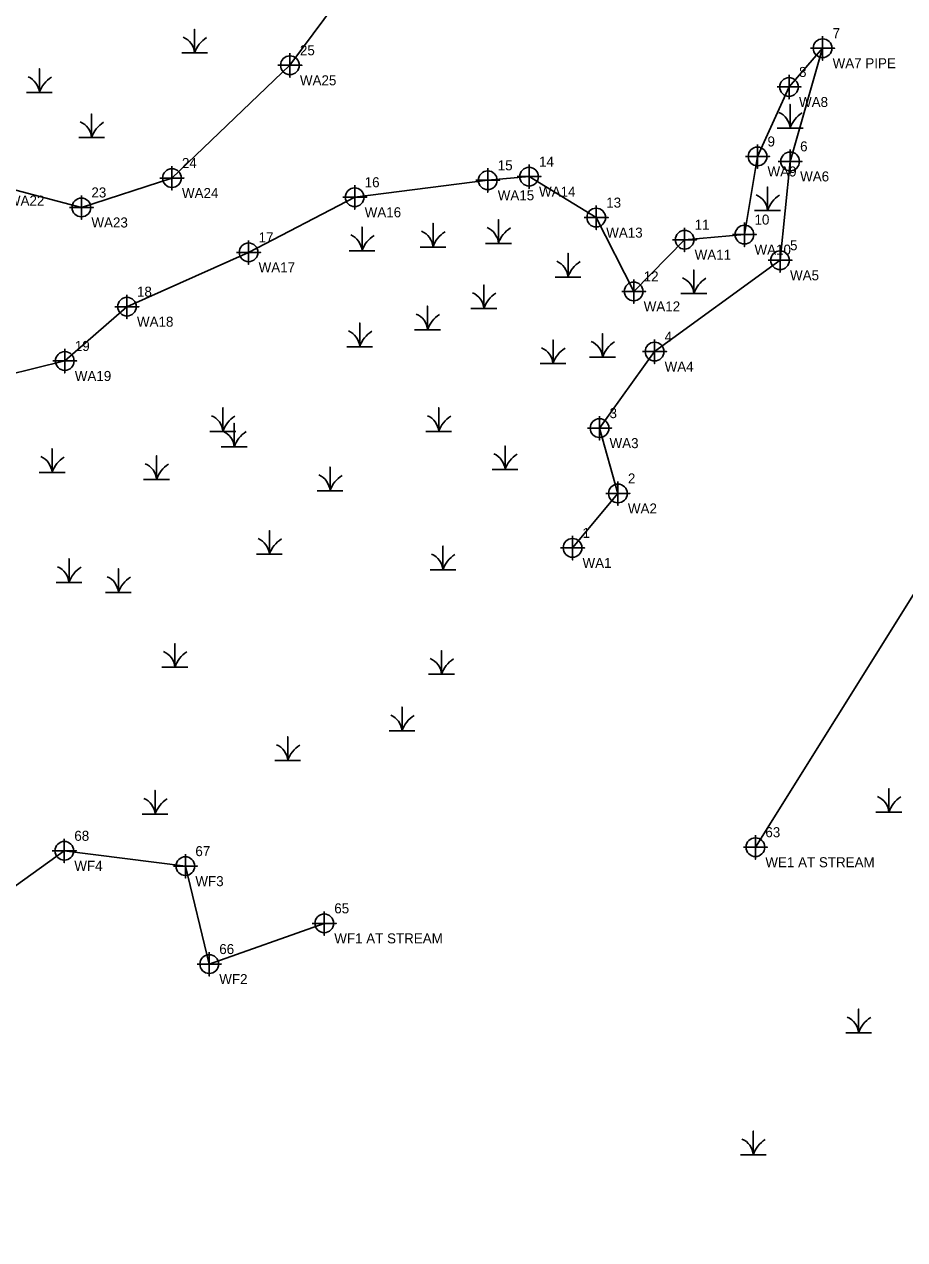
# Model space of a CAD drawing. Extents: x 2189822 to 2191198, y 387253 to 388663.
# Drawn here: x 2190236.7 to 2190456.6, y 387833.3 to 388136.9 of the extents above; entities that cross this region are included whole.
import ezdxf

# ---------------------------------------------------------------- set-up
doc = ezdxf.new("R2010")
doc.units = 0
for name, color, linetype in [('Structure020030_Alleghany', 7, 'Continuous'), ('Structure040008_Ashe', 7, 'Continuous'), ('Structure090007_Brunswick', 7, 'Continuous'), ('Structure620024_Moore', 7, 'Continuous'), ('Structure780124_Rockingham', 7, 'Continuous')]:
    doc.layers.add(name, color=color, linetype=linetype)

msp = doc.modelspace()

# ---------------------------------------------------------------- linework, layer by layer
at = {"layer": 'Structure020030_Alleghany'}
for points in [[(2190436.1, 388133.93), (2190436.1, 388127.93), (2190436.1, 388130.93), (2190439.1, 388130.93), (2190433.1, 388130.93)], [(2190303.02, 388129.66), (2190303.02, 388123.66), (2190303.02, 388126.66), (2190306.02, 388126.66), (2190300.02, 388126.66)], [(2190427.71, 388124.24), (2190427.71, 388118.24), (2190427.71, 388121.24), (2190430.71, 388121.24), (2190424.71, 388121.24)], [(2190419.84, 388106.88), (2190419.84, 388100.88), (2190419.84, 388103.88), (2190422.84, 388103.88), (2190416.84, 388103.88)], [(2190427.98, 388105.65), (2190427.98, 388099.65), (2190427.98, 388102.65), (2190430.98, 388102.65), (2190424.98, 388102.65)], [(2190273.55, 388101.49), (2190273.55, 388095.49), (2190273.55, 388098.49), (2190276.55, 388098.49), (2190270.55, 388098.49)], [(2190352.44, 388100.93), (2190352.44, 388094.93), (2190352.44, 388097.93), (2190355.44, 388097.93), (2190349.44, 388097.93)], [(2190362.76, 388101.84), (2190362.76, 388095.84), (2190362.76, 388098.84), (2190365.76, 388098.84), (2190359.76, 388098.84)], [(2190250.93, 388094.14), (2190250.93, 388088.14), (2190250.93, 388091.14), (2190253.93, 388091.14), (2190247.93, 388091.14)], [(2190319.2, 388096.69), (2190319.2, 388090.69), (2190319.2, 388093.69), (2190322.2, 388093.69), (2190316.2, 388093.69)], [(2190379.54, 388091.61), (2190379.54, 388085.61), (2190379.54, 388088.61), (2190382.54, 388088.61), (2190376.54, 388088.61)], [(2190401.63, 388086.09), (2190401.63, 388080.09), (2190401.63, 388083.09), (2190404.63, 388083.09), (2190398.63, 388083.09)], [(2190416.58, 388087.36), (2190416.58, 388081.36), (2190416.58, 388084.36), (2190419.58, 388084.36), (2190413.58, 388084.36)], [(2190292.7, 388082.93), (2190292.7, 388076.93), (2190292.7, 388079.93), (2190295.7, 388079.93), (2190289.7, 388079.93)], [(2190425.46, 388080.95), (2190425.46, 388074.95), (2190425.46, 388077.95), (2190428.46, 388077.95), (2190422.46, 388077.95)], [(2190388.9, 388073.17), (2190388.9, 388067.17), (2190388.9, 388070.17), (2190391.9, 388070.17), (2190385.9, 388070.17)], [(2190262.31, 388069.36), (2190262.31, 388063.36), (2190262.31, 388066.36), (2190265.31, 388066.36), (2190259.31, 388066.36)], [(2190394.13, 388058.14), (2190394.13, 388052.14), (2190394.13, 388055.14), (2190397.13, 388055.14), (2190391.13, 388055.14)], [(2190246.78, 388055.8), (2190246.78, 388049.8), (2190246.78, 388052.8), (2190249.78, 388052.8), (2190243.78, 388052.8)], [(2190380.37, 388039.02), (2190380.37, 388033.02), (2190380.37, 388036.02), (2190383.37, 388036.02), (2190377.37, 388036.02)], [(2190384.96, 388022.7), (2190384.96, 388016.7), (2190384.96, 388019.7), (2190387.96, 388019.7), (2190381.96, 388019.7)], [(2190373.62, 388009.11), (2190373.62, 388003.11), (2190373.62, 388006.11), (2190376.62, 388006.11), (2190370.62, 388006.11)], [(2190246.66, 387933.44), (2190246.66, 387927.44), (2190246.66, 387930.44), (2190249.66, 387930.44), (2190243.66, 387930.44)], [(2190419.3, 387934.34), (2190419.3, 387928.34), (2190419.3, 387931.34), (2190422.3, 387931.34), (2190416.3, 387931.34)], [(2190276.9, 387929.61), (2190276.9, 387923.61), (2190276.9, 387926.61), (2190279.9, 387926.61), (2190273.9, 387926.61)], [(2190311.6, 387915.32), (2190311.6, 387909.32), (2190311.6, 387912.32), (2190314.6, 387912.32), (2190308.6, 387912.32)], [(2190282.87, 387905.15), (2190282.87, 387899.15), (2190282.87, 387902.15), (2190285.87, 387902.15), (2190279.87, 387902.15)]]:
    msp.add_lwpolyline(points, dxfattribs=at)
for centre in [(2190436.1, 388130.93), (2190303.02, 388126.66), (2190427.71, 388121.24), (2190419.84, 388103.88), (2190427.98, 388102.65), (2190273.55, 388098.49), (2190352.44, 388097.93), (2190362.76, 388098.84), (2190319.2, 388093.69), (2190250.93, 388091.14), (2190379.54, 388088.61), (2190401.63, 388083.09), (2190416.58, 388084.36), (2190292.7, 388079.93), (2190425.46, 388077.95), (2190388.9, 388070.17), (2190262.31, 388066.36), (2190394.13, 388055.14), (2190246.78, 388052.8), (2190380.37, 388036.02), (2190384.96, 388019.7), (2190373.62, 388006.11), (2190246.66, 387930.44), (2190419.3, 387931.34), (2190276.9, 387926.61), (2190311.6, 387912.32), (2190282.87, 387902.15)]:
    msp.add_circle(centre, 2.34, dxfattribs=at)
at = {"layer": 'Structure620024_Moore'}
for points in [[(2190230.07, 388096.61), (2190250.93, 388091.14), (2190273.55, 388098.49), (2190303.02, 388126.66), (2190317.29, 388145.97)], [(2190373.62, 388006.11), (2190384.96, 388019.7), (2190380.37, 388036.02), (2190394.13, 388055.14), (2190425.46, 388077.95), (2190427.98, 388102.65), (2190436.1, 388130.93), (2190427.71, 388121.24), (2190419.84, 388103.88), (2190416.58, 388084.36), (2190401.63, 388083.09), (2190388.9, 388070.17), (2190379.54, 388088.61), (2190362.76, 388098.84), (2190352.44, 388097.93), (2190319.2, 388093.69), (2190292.7, 388079.93), (2190262.31, 388066.36), (2190246.78, 388052.8), (2190217.1, 388045.51)], [(2190419.3, 387931.34), (2190459.66, 387995.83)], [(2190311.6, 387912.32), (2190282.87, 387902.15), (2190276.9, 387926.61), (2190246.66, 387930.44), (2190212.31, 387905.81), (2190187.82, 387866.13), (2190141.4, 387841.78), (2190098.41, 387819.25)]]:
    msp.add_lwpolyline(points, dxfattribs=at)
at = {"layer": 'Structure780124_Rockingham'}
for p, q in [((2190279.21, 388132.42), (2190279.21, 388132.42)), ((2190240.43, 388122.54), (2190240.43, 388122.54)), ((2190427.98, 388113.65), (2190427.98, 388113.65)), ((2190253.47, 388111.25), (2190253.47, 388111.25)), ((2190422.34, 388093.03), (2190422.34, 388093.03)), ((2190355.11, 388084.86), (2190355.11, 388084.86)), ((2190321.04, 388083.01), (2190321.04, 388083.01)), ((2190338.77, 388083.93), (2190338.77, 388083.93)), ((2190372.49, 388076.45), (2190372.49, 388076.45)), ((2190403.92, 388072.3), (2190403.92, 388072.3)), ((2190351.48, 388068.57), (2190351.48, 388068.57)), ((2190337.38, 388063.28), (2190337.38, 388063.28)), ((2190320.45, 388059.05), (2190320.45, 388059.05)), ((2190368.75, 388054.81), (2190368.75, 388054.81)), ((2190381.13, 388056.4), (2190381.13, 388056.4)), ((2190286.26, 388037.88), (2190286.26, 388037.88)), ((2190340.2, 388037.88), (2190340.2, 388037.88)), ((2190289.08, 388034), (2190289.08, 388034)), ((2190243.6, 388027.65), (2190243.6, 388027.65)), ((2190356.76, 388028.36), (2190356.76, 388028.36)), ((2190269.69, 388025.89), (2190269.69, 388025.89)), ((2190313.05, 388023.06), (2190313.05, 388023.06)), ((2190297.89, 388007.19), (2190297.89, 388007.19)), ((2190341.25, 388003.31), (2190341.25, 388003.31)), ((2190247.83, 388000.14), (2190247.83, 388000.14)), ((2190260.17, 387997.67), (2190260.17, 387997.67)), ((2190274.27, 387978.97), (2190274.27, 387978.97)), ((2190340.9, 387977.21), (2190340.9, 387977.21)), ((2190331.03, 387963.1), (2190331.03, 387963.1)), ((2190302.48, 387955.69), (2190302.48, 387955.69)), ((2190269.34, 387942.28), (2190269.34, 387942.28)), ((2190452.66, 387942.75), (2190452.66, 387942.75)), ((2190445.1, 387887.65), (2190445.1, 387887.65)), ((2190418.77, 387857.2), (2190418.77, 387857.2))]:
    msp.add_line(p, q, dxfattribs=at)
for points in [[(2190275.98, 388129.74), (2190279.21, 388129.74), (2190279.21, 388135.66), (2190279.21, 388129.74), (2190282.44, 388129.74)], [(2190237.21, 388119.87), (2190240.43, 388119.87), (2190240.43, 388125.78), (2190240.43, 388119.87), (2190243.66, 388119.87)], [(2190424.75, 388110.98), (2190427.98, 388110.98), (2190427.98, 388116.89), (2190427.98, 388110.98), (2190431.2, 388110.98)], [(2190250.25, 388108.58), (2190253.48, 388108.58), (2190253.48, 388114.5), (2190253.48, 388108.58), (2190256.7, 388108.58)], [(2190419.11, 388090.36), (2190422.34, 388090.36), (2190422.34, 388096.28), (2190422.34, 388090.36), (2190425.56, 388090.36)], [(2190351.89, 388082.18), (2190355.11, 388082.18), (2190355.11, 388088.1), (2190355.11, 388082.18), (2190358.34, 388082.18)], [(2190317.82, 388080.34), (2190321.04, 388080.34), (2190321.04, 388086.26), (2190321.04, 388080.34), (2190324.27, 388080.34)], [(2190335.54, 388081.26), (2190338.77, 388081.26), (2190338.77, 388087.18), (2190338.77, 388081.26), (2190341.99, 388081.26)], [(2190369.27, 388073.77), (2190372.5, 388073.77), (2190372.5, 388079.69), (2190372.5, 388073.77), (2190375.72, 388073.77)], [(2190400.7, 388069.63), (2190403.92, 388069.63), (2190403.92, 388075.54), (2190403.92, 388069.63), (2190407.15, 388069.63)], [(2190348.25, 388065.9), (2190351.48, 388065.9), (2190351.48, 388071.81), (2190351.48, 388065.9), (2190354.7, 388065.9)], [(2190334.15, 388060.6), (2190337.38, 388060.6), (2190337.38, 388066.52), (2190337.38, 388060.6), (2190340.6, 388060.6)], [(2190317.23, 388056.37), (2190320.46, 388056.37), (2190320.46, 388062.29), (2190320.46, 388056.37), (2190323.68, 388056.37)], [(2190365.53, 388052.14), (2190368.75, 388052.14), (2190368.75, 388058.06), (2190368.75, 388052.14), (2190371.98, 388052.14)], [(2190377.9, 388053.73), (2190381.13, 388053.73), (2190381.13, 388059.65), (2190381.13, 388053.73), (2190384.35, 388053.73)], [(2190283.03, 388035.21), (2190286.26, 388035.21), (2190286.26, 388041.12), (2190286.26, 388035.21), (2190289.49, 388035.21)], [(2190336.97, 388035.21), (2190340.2, 388035.21), (2190340.2, 388041.12), (2190340.2, 388035.21), (2190343.42, 388035.21)], [(2190285.85, 388031.33), (2190289.08, 388031.33), (2190289.08, 388037.24), (2190289.08, 388031.33), (2190292.31, 388031.33)], [(2190240.38, 388024.98), (2190243.6, 388024.98), (2190243.6, 388030.89), (2190243.6, 388024.98), (2190246.83, 388024.98)], [(2190353.54, 388025.68), (2190356.77, 388025.68), (2190356.77, 388031.6), (2190356.77, 388025.68), (2190359.99, 388025.68)], [(2190266.47, 388023.21), (2190269.69, 388023.21), (2190269.69, 388029.13), (2190269.69, 388023.21), (2190272.92, 388023.21)], [(2190309.83, 388020.39), (2190313.05, 388020.39), (2190313.05, 388026.31), (2190313.05, 388020.39), (2190316.28, 388020.39)], [(2190294.67, 388004.52), (2190297.89, 388004.52), (2190297.89, 388010.43), (2190297.89, 388004.52), (2190301.12, 388004.52)], [(2190338.03, 388000.64), (2190341.25, 388000.64), (2190341.25, 388006.55), (2190341.25, 388000.64), (2190344.48, 388000.64)], [(2190244.61, 387997.46), (2190247.83, 387997.46), (2190247.83, 388003.38), (2190247.83, 387997.46), (2190251.06, 387997.46)], [(2190256.95, 387994.99), (2190260.17, 387994.99), (2190260.17, 388000.91), (2190260.17, 387994.99), (2190263.4, 387994.99)], [(2190271.05, 387976.3), (2190274.27, 387976.3), (2190274.27, 387982.21), (2190274.27, 387976.3), (2190277.5, 387976.3)], [(2190337.68, 387974.53), (2190340.9, 387974.53), (2190340.9, 387980.45), (2190340.9, 387974.53), (2190344.13, 387974.53)], [(2190327.81, 387960.42), (2190331.03, 387960.42), (2190331.03, 387966.34), (2190331.03, 387960.42), (2190334.26, 387960.42)], [(2190299.25, 387953.01), (2190302.48, 387953.01), (2190302.48, 387958.93), (2190302.48, 387953.01), (2190305.7, 387953.01)], [(2190266.11, 387939.61), (2190269.34, 387939.61), (2190269.34, 387945.53), (2190269.34, 387939.61), (2190272.56, 387939.61)], [(2190449.43, 387940.07), (2190452.66, 387940.07), (2190452.66, 387945.99), (2190452.66, 387940.07), (2190455.88, 387940.07)], [(2190441.87, 387884.98), (2190445.1, 387884.98), (2190445.1, 387890.89), (2190445.1, 387884.98), (2190448.33, 387884.98)], [(2190415.55, 387854.52), (2190418.77, 387854.52), (2190418.77, 387860.44), (2190418.77, 387854.52), (2190422, 387854.52)]]:
    msp.add_lwpolyline(points, dxfattribs=at)
for centre, radius, start, end in [((2190274.61, 388129.41), 4.61, 4.1403, 67.535), ((2190286.05, 388127.47), 7.21, 122.1274, 161.6222), ((2190235.83, 388119.53), 4.61, 4.1403, 67.535), ((2190247.27, 388117.59), 7.21, 122.1274, 161.6222), ((2190248.88, 388108.25), 4.61, 4.1403, 67.535), ((2190260.32, 388106.31), 7.21, 122.1274, 161.6222), ((2190423.38, 388110.64), 4.61, 4.1403, 67.535), ((2190434.82, 388108.7), 7.21, 122.1274, 161.6222), ((2190417.74, 388090.03), 4.61, 4.1403, 67.535), ((2190429.18, 388088.09), 7.21, 122.1274, 161.6222), ((2190334.17, 388080.93), 4.61, 4.1403, 67.535), ((2190345.61, 388078.99), 7.21, 122.1274, 161.6222), ((2190350.51, 388081.85), 4.61, 4.1403, 67.535), ((2190361.95, 388079.91), 7.21, 122.1274, 161.6222), ((2190316.44, 388080.01), 4.61, 4.1403, 67.535), ((2190327.88, 388078.07), 7.21, 122.1274, 161.6222), ((2190367.9, 388073.44), 4.61, 4.1403, 67.535), ((2190379.34, 388071.5), 7.21, 122.1274, 161.6222), ((2190399.32, 388069.29), 4.61, 4.1403, 67.535), ((2190410.76, 388067.35), 7.21, 122.1274, 161.6222), ((2190346.88, 388065.56), 4.61, 4.1403, 67.535), ((2190358.32, 388063.62), 7.21, 122.1274, 161.6222), ((2190332.78, 388060.27), 4.61, 4.1403, 67.535), ((2190344.22, 388058.33), 7.21, 122.1274, 161.6222), ((2190315.86, 388056.04), 4.61, 4.1403, 67.535), ((2190327.3, 388054.1), 7.21, 122.1274, 161.6222), ((2190376.53, 388053.4), 4.61, 4.1403, 67.535), ((2190387.97, 388051.46), 7.21, 122.1274, 161.6222), ((2190364.15, 388051.8), 4.61, 4.1403, 67.535), ((2190375.59, 388049.87), 7.21, 122.1274, 161.6222), ((2190281.66, 388034.87), 4.61, 4.1403, 67.535), ((2190293.1, 388032.93), 7.21, 122.1274, 161.6222), ((2190335.6, 388034.87), 4.61, 4.1403, 67.535), ((2190347.04, 388032.93), 7.21, 122.1274, 161.6222), ((2190284.48, 388030.99), 4.61, 4.1403, 67.535), ((2190295.92, 388029.05), 7.21, 122.1274, 161.6222), ((2190239, 388024.64), 4.61, 4.1403, 67.535), ((2190250.45, 388022.7), 7.21, 122.1274, 161.6222), ((2190265.09, 388022.88), 4.61, 4.1403, 67.535), ((2190276.53, 388020.94), 7.21, 122.1274, 161.6222), ((2190352.17, 388025.35), 4.61, 4.1403, 67.535), ((2190363.61, 388023.41), 7.21, 122.1274, 161.6222), ((2190308.45, 388020.06), 4.61, 4.1403, 67.535), ((2190319.89, 388018.12), 7.21, 122.1274, 161.6222), ((2190293.29, 388004.18), 4.61, 4.1403, 67.535), ((2190304.73, 388002.24), 7.21, 122.1274, 161.6222), ((2190336.65, 388000.3), 4.61, 4.1403, 67.535), ((2190348.09, 387998.36), 7.21, 122.1274, 161.6222), ((2190243.23, 387997.13), 4.61, 4.1403, 67.535), ((2190254.68, 387995.19), 7.21, 122.1274, 161.6222), ((2190255.57, 387994.66), 4.61, 4.1403, 67.535), ((2190267.01, 387992.72), 7.21, 122.1274, 161.6222), ((2190269.67, 387975.96), 4.61, 4.1403, 67.535), ((2190281.12, 387974.02), 7.21, 122.1274, 161.6222), ((2190336.3, 387974.2), 4.61, 4.1403, 67.535), ((2190347.74, 387972.26), 7.21, 122.1274, 161.6222), ((2190326.43, 387960.09), 4.61, 4.1403, 67.535), ((2190337.87, 387958.15), 7.21, 122.1274, 161.6222), ((2190297.88, 387952.68), 4.61, 4.1403, 67.535), ((2190309.32, 387950.74), 7.21, 122.1274, 161.6222), ((2190264.74, 387939.28), 4.61, 4.1403, 67.535), ((2190276.18, 387937.34), 7.21, 122.1274, 161.6222), ((2190448.06, 387939.74), 4.61, 4.1403, 67.535), ((2190459.5, 387937.8), 7.21, 122.1274, 161.6222), ((2190440.5, 387884.64), 4.61, 4.1403, 67.535), ((2190451.94, 387882.7), 7.21, 122.1274, 161.6222), ((2190414.18, 387854.19), 4.61, 4.1403, 67.535), ((2190425.62, 387852.25), 7.21, 122.1274, 161.6222)]:
    msp.add_arc(centre, radius, start, end, dxfattribs=at)

# ---------------------------------------------------------------- texts
at = {"layer": 'Structure040008_Ashe'}
for s, p in [('7', (2190438.6, 388133.43)), ('25', (2190305.52, 388129.16)), ('8', (2190430.21, 388123.74)), ('9', (2190422.34, 388106.38)), ('6', (2190430.48, 388105.15)), ('24', (2190276.05, 388100.99)), ('15', (2190354.94, 388100.43)), ('14', (2190365.26, 388101.34)), ('16', (2190321.7, 388096.19)), ('23', (2190253.43, 388093.64)), ('13', (2190382.04, 388091.11)), ('11', (2190404.13, 388085.59)), ('10', (2190419.08, 388086.86)), ('17', (2190295.2, 388082.43)), ('5', (2190427.96, 388080.45)), ('12', (2190391.4, 388072.67)), ('18', (2190264.81, 388068.86)), ('19', (2190249.28, 388055.3)), ('4', (2190396.63, 388057.64)), ('3', (2190382.87, 388038.52)), ('2', (2190387.46, 388022.2)), ('1', (2190376.12, 388008.61)), ('63', (2190421.8, 387933.84)), ('68', (2190249.16, 387932.94)), ('67', (2190279.4, 387929.11)), ('65', (2190314.1, 387914.82)), ('66', (2190285.37, 387904.65))]:
    msp.add_text(s, height=2.5, dxfattribs=at).set_placement(p)
at = {"layer": 'Structure090007_Brunswick'}
for s, p in [('WA7 PIPE', (2190438.6, 388125.93)), ('WA25', (2190305.52, 388121.66)), ('WA8', (2190430.21, 388116.24)), ('WA9', (2190422.34, 388098.88)), ('WA6', (2190430.48, 388097.65)), ('WA22', (2190232.57, 388091.61)), ('WA24', (2190276.05, 388093.49)), ('WA15', (2190354.94, 388092.93)), ('WA14', (2190365.26, 388093.84)), ('WA16', (2190321.7, 388088.69)), ('WA23', (2190253.43, 388086.14)), ('WA13', (2190382.04, 388083.61)), ('WA10', (2190419.08, 388079.36)), ('WA11', (2190404.13, 388078.09)), ('WA17', (2190295.2, 388074.93)), ('WA5', (2190427.96, 388072.95)), ('WA12', (2190391.4, 388065.17)), ('WA18', (2190264.81, 388061.36)), ('WA4', (2190396.63, 388050.14)), ('WA19', (2190249.28, 388047.8)), ('WA3', (2190382.87, 388031.02)), ('WA2', (2190387.46, 388014.7)), ('WA1', (2190376.12, 388001.11)), ('WF4', (2190249.16, 387925.44)), ('WE1 AT STREAM', (2190421.8, 387926.34)), ('WF3', (2190279.4, 387921.61)), ('WF1 AT STREAM', (2190314.1, 387907.32)), ('WF2', (2190285.37, 387897.15))]:
    msp.add_text(s, height=2.5, dxfattribs=at).set_placement(p)

doc.saveas('drawing.dxf')
